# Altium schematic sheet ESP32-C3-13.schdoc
size 21 x 30 mm
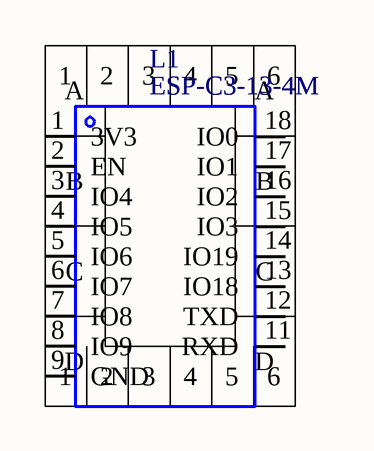
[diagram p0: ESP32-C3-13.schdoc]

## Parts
L1  ESP-C3-13-4M

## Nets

Not connected (* = marked no-connect by the designer): L1 1(3V3) 2(EN) 3(IO4) 4(IO5) 5(IO6) 6(IO7) 7(IO8) 8(IO9) 9(GND) 10(IO10) 11(RXD) 12(TXD) 13(IO18) 14(IO19) 15(IO3) 16(IO2) 17(IO1) 18(IO0)

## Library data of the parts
L1 = ESP-C3-13-4M: Manufacturer: Ai-Thinker(安信可); Convert to PCB: yes; Origin Footprint: WIRELM-SMD_ESP-C3-13-4M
